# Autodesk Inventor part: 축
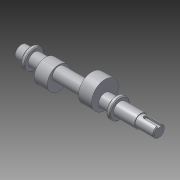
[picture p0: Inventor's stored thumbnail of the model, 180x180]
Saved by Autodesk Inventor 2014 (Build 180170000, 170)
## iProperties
Created: 2014-12
Part Number: 축
Material: 알루미늄 6061
Document SubType Name: Modeling
Designer: Owner
Mass: 170.354 g
Surface Area: 153.402 cm^2
Volume: 62.8614 cm^3
Density: 2.71 g/cm^3
Appearance: 알루미늄 - 평지
Author: Owner
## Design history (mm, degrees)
sketch "스케치1"
  geometry: L1 (-90, 0)-(90, 0); L2 (-90, 0)-(-90, 7.5); L3 (-90, 7.5)-(-66, 7.5); L4 (-66, 7.5)-(-66, 8.5); L5 (-66, 8.5)-(-39, 8.5); L6 (-39, 8.5)-(-39, 13); L7 (-39, 13)-(-34, 13); L8 (-34, 13)-(-34, 8.5); L9 (-34, 8.5)-(72, 8.5); L10 (72, 8.5)-(72, 13); L11 (72, 13)-(77, 13); L12 (77, 13)-(77, 8.5); L13 (77, 8.5)-(90, 8.5); L14 (90, 8.5)-(90, 0); 7 further points
  constraints: 28 end point, 11 parallel, 7 midpoint, 3 horizontal alignment, 2 coincident, 2 perpendicular, 1 horizontal
  dimensions: "d0" = 180 distance of L1.start L1.end; "d1" = 15 diameter of L3 L1; "d2" = 17 diameter of point (-52.5, 8.5) L1; "d3" = 26 diameter of point (-36.5, 13) L1; "d4" = 24 distance of L2.end L3.end; "d5" = 27 distance of L4.end L5.end; "d6" = 5 distance of L6.end L7.end; "d7" = 13 distance of L12.end L13.end; "d8" = 5 distance of L10.end L11.end
revolve "회전1" sketch "스케치1" stored, may be unused: angle "d9" = 90 deg
node "작업 평면1"
node "작업 평면2"
node "작업 평면3"
sketch "스케치4"
  geometry: C1 r 15 at (-5, 0); 1 further point
  constraints: 1 centre point, 1 horizontal alignment
  dimensions: "d16" = 30 diameter of C1; "d17" = 5 distance of point (0, 0) C1.centre
extrude "돌출2" join sketch "스케치4" distance "d18" = 17; taper "d19" = 0 deg
node "작업 평면4"
sketch "스케치5"
  geometry: L1 (72.5, 2.5)-(90, 2.5); L2 (90, 2.5)-(90, -2.5); L3 (90, -2.5)-(72.5, -2.5); L4 (70, 0)-(70, 0); L5 (90, 7.5)-(90, -7.5) reference; A1 r 2.5 centre (72.5, 0) between (72.5, 2.5) and (70, 0); A2 r 2.5 centre (72.5, 0) between (70, 0) and (72.5, -2.5); 6 further points
  constraints: 8 end point, 4 point on circle, 4 point on line, 4 tangent, 3 midpoint, 2 centre point, 2 parallel, 1 coincident, 1 concentric, 1 horizontal, 1 horizontal alignment, 1 perpendicular
  dimensions: "d21" = 20 distance of point (70, 2.5) L1.end; "d22" = 5 distance of point (70, -2.5) point (70, 2.5); "d23" = 2.5 radius of A1
extrude "돌출3" cut sketch "스케치5" distance "d24" = 3; taper "d25" = 0 deg
chamfer "모따기1" distance "d26" = 1; stored, may be unused: second distance "d27" = 2, angle "d28" = 45 deg
chamfer "모따기3" distance "d32" = 1; stored, may be unused: second distance "d33" = 2, angle "d34" = 45 deg
node "작업 평면5"
sketch "스케치7"
  geometry: C1 r 17.5 at (6, 0); 1 further point
  constraints: 1 centre point, 1 horizontal alignment
  dimensions: "d38" = 35 diameter of C1; "d39" = 6 distance of C1.centre point (0, 0)
extrude "돌출4" join sketch "스케치7" distance "d40" = 17; taper "d41" = 0 deg
chamfer "모따기4" distance "d43" = 1; stored, may be unused: second distance "d44" = 2, angle "d45" = 45 deg
node "솔리드1"
other parameters: "d10" = -60.5, "d15" = -32.5, "d20" = 7.5, "d35" = 14.5
